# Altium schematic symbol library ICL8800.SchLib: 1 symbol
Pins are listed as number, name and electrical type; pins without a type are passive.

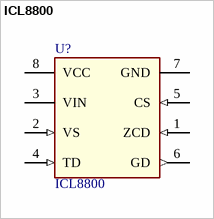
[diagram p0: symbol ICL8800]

## ICL8800
designator U?
Single Stage Flyback Controller; Manufacturer: Infineon Technologies
pins: 1 ZCD (in) "Zero crossing detection", 2 VS (in) "Voltage Sense", 3 VIN (power) "Input voltage detection", 4 TD (in) "THD correction", 5 CS (in) "MOSFET current sense and secondary side over voltage protection", 6 GD (out) "Gate drive", 7 GND (power) "Ground", 8 VCC (power) "Power supply"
